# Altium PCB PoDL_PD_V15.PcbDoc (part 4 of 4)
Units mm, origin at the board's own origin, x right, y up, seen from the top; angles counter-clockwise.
Board outline 145 x 75 mm, 4 copper layers (Top Layer, Signal Layer 2, Signal Layer 3, Bottom Layer), stack 1.586 mm thick; 346 components, 228 nets, 1035 pads, 619 vias.
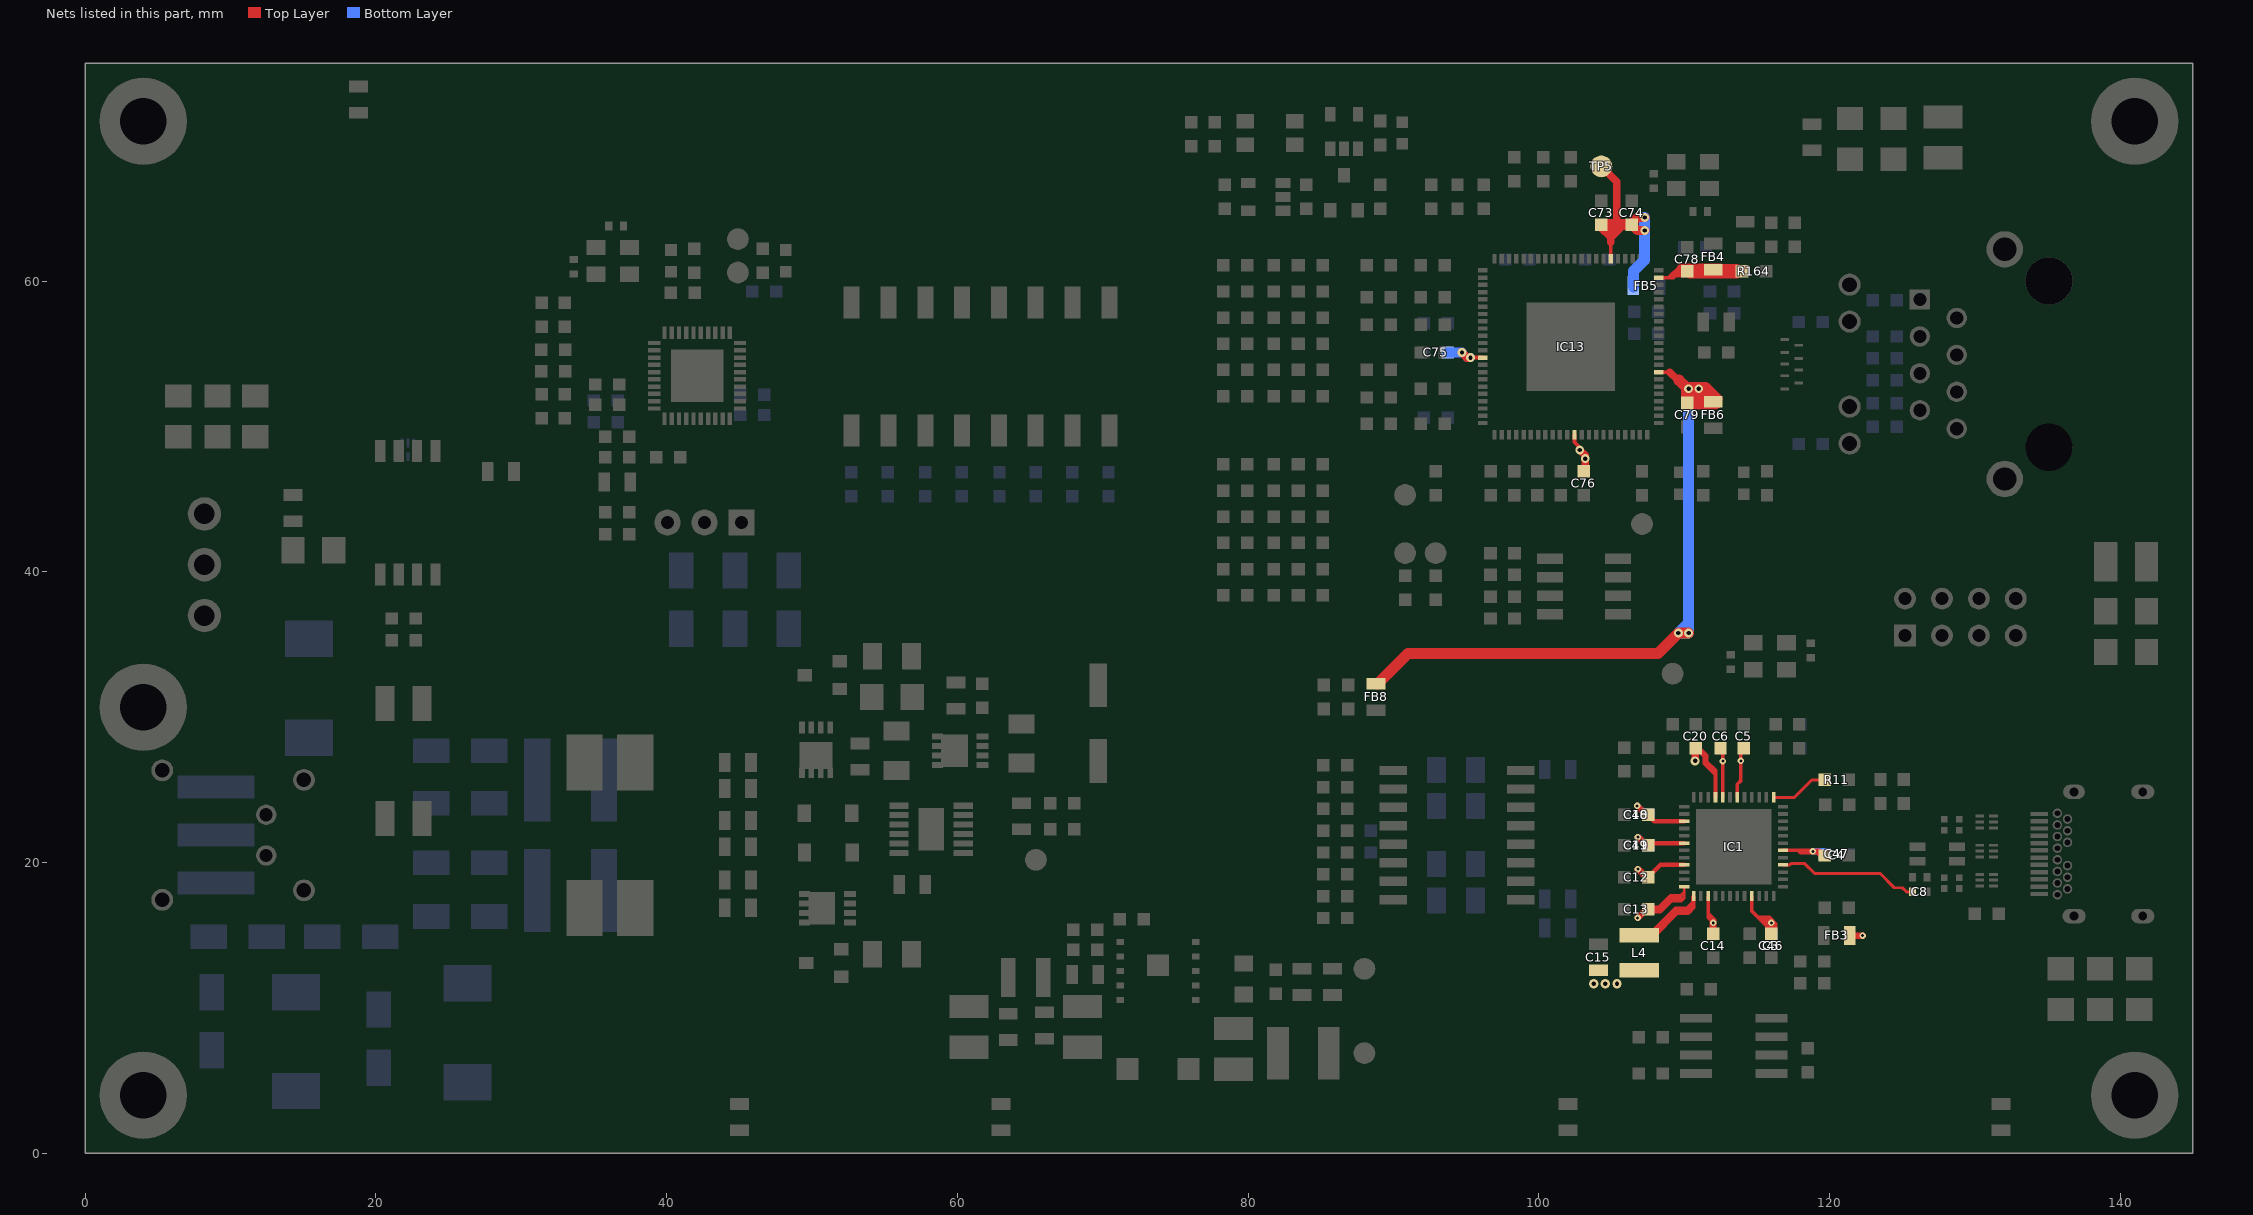
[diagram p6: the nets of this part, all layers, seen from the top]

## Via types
v1: diameter 0.6, hole 0.3, Top Layer to Bottom Layer, tented both sides, 350 vias
v2: diameter 0.45, hole 0.2, Top Layer to Bottom Layer, tented both sides, 137 vias
v3: diameter 0.635, hole 0.3, Top Layer to Bottom Layer, tented both sides, 77 vias
v4: diameter 1.016, hole 0.508, Top Layer to Bottom Layer, 40 vias
v5: diameter 1.016, hole 0.457, Top Layer to Bottom Layer, tented both sides, 8 vias
v6: diameter 0.762, hole 0.381, Top Layer to Bottom Layer, tented both sides, 7 vias

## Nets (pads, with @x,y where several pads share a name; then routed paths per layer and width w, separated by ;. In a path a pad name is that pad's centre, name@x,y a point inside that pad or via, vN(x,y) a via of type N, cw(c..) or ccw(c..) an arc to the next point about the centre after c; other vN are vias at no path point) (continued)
USB3TX_P: C8.2 IC1.28 | length 9.8
  Top Layer w0.206: IC1.28@116.8,19.85 117.253,19.85 117.336,19.934 118.301,19.934 118.967,19.267 123.461,19.267 124.451,18.277 125.005,18.277 125.302,17.98 C8.2@125.725,17.98
USBRBIAS: IC1.37 R11.1 | length 4
  Top Layer w0.203: IC1.37@116.15,24.5 117.595,24.5 118.8,25.705 R11.1@119.675,25.705
VDD12: C3.1 C4.1 C5.1 C6.1 C14.1 C15.2 C46.1 C47.1 FB3.2 IC1.15 IC1.21 IC1.30 IC1.42 IC1.44 L4.2 | length 24.5
  Top Layer w0.25: IC1.15@111.65,17.7 111.65,16.521 ; C14.1@111.995,15.061 111.868,15.188 111.868,16.013 111.65,16.231 111.65,16.521 ; C14.1@112.1,15.166 112.1,15.861 112.1,16.071 111.65,16.521 ; IC1.44@112.65,24.5 C6.1@112.65,27.73 ; IC1.42@113.65,24.5 113.65,25.405 113.9,25.655 C5.1@113.9,27.48 ; IC1.21@114.65,17.7 114.65,16.681 115.1,16.231 ; C3.1@115.7,15.188 115.7,15.631 115.413,15.918 115.1,16.231 ; C3.1@116,15.081 116.3,15.381 116.3,15.807 115.876,16.231 115.55,16.231 115.1,16.231 ; IC1.30@116.8,20.85 117.828,20.85 ; 117.828,20.85 117.978,20.7 118.853,20.7 119.125,20.7 119.345,20.48 119.7,20.48 119.33,20.85 118.853,20.85 117.828,20.85
  Top Layer w0.45: FB3.2@121.4,14.98 v2(122.274,14.98)
  Top Layer w0.508: 115.55,16.055 115.837,15.768 116,15.605 C3.1@116,15.081
  Bottom Layer w0.45: v2(118.853,20.78) C47.1@119.627,20.78
  Bottom Layer w0.508: C46.1@116,15.08 v2(116,15.855)
  other v2: 111.995,15.861 112.655,26.985 113.9,27
  other v3: 103.775,11.68 104.575,11.68 105.375,11.68
VDD12_SW_OUT: IC1.13 L4.1 | length 12.7
  Top Layer w0.25: L4.1@107.477,14.927 109.405,16.855 110.18,16.855 110.6,17.275 IC1.13@110.6,17.655 ; L4.1@107.672,14.927 109.4,16.655 110.25,16.655 110.575,16.98 110.65,17.055 ; L4.1@107.936,14.927 109.53,16.521 110.266,16.521 110.325,16.58 110.65,16.905 110.65,17.055 ; IC1.13@110.65,17.7 110.65,17.275 110.65,17.055
VDD25: C10.1 C11.1 C12.1 C13.1 C20.1 C48.1 C49.1 IC1.3 IC1.6 IC1.9 IC1.12 IC1.45 | length 29.6
  Top Layer w0.2: C13.1@107.5,16.78 C13.1@107.606,16.675 ; C13.1@107.606,16.6 108.38,16.6 109.13,17.35 109.77,17.35 110,17.58 110,17.98 ; C13.1@107.67,16.95 108.245,16.95 109.045,17.75 109.77,17.75 110,17.98 ; IC1.12@110,18.35 110,17.98
  Top Layer w0.25: C13.1@107.5,16.78 108.335,16.78 109.087,17.532 109.675,17.532 109.77,17.627 109.77,17.75 ; C20.1@110.884,27.804 111.4,27.288 111.4,26.805 112.15,26.055 ; C20.1@111.051,27.879 111.55,27.38 111.55,26.955 112.15,26.355 112.15,26.055 ; IC1.45@112.15,24.5 112.15,26.055
  Top Layer w0.305: C12.1@107.5,18.98 108.37,19.85 IC1.9@110,19.85 ; C11.1@107.5,21.18 107.67,21.35 IC1.6@110,21.35 ; C10.1@107.5,23.28 107.931,22.85 IC1.3@110,22.85
  Top Layer w0.45: v2(106.763,23.912) C10.1@107.345,23.33 ; v2(106.8,16.2) C13.1@107.382,16.782 ; v2(106.813,19.562) C12.1@107.395,18.98 ; v2(106.813,21.762) C11.1@107.395,21.18 ; C13.1@107.5,16.78 C13.1@107.67,16.95
  Top Layer w0.508: v3(110.75,27.005) C20.1@110.75,27.78
  Bottom Layer w0.45: v2(106.763,23.912) 107.375,23.3 C48.1@107.526,23.3 ; v2(106.813,21.762) C49.1@107.425,21.15
VDD33TXRX1: C79.1 FB6.2 FB8.2 IC13.74 | length 51.8
  Top Layer w0.254: IC13.74@108.25,53.75 109.012,53.75
  Top Layer w0.508: 109.012,53.75 109.572,53.19
  Top Layer w0.762: FB8.2@88.9,32.3 91,34.4 108.2,34.4 v1(109.6,35.8) v1(110.3,35.8) ; 109.647,53.19 v1@110.155,52.682 ; C79.1@110.155,51.666 110.155,52.3 ; 111.125,51.7 111.125,51.712 ; 111.468,52.3 110.155,52.3 ; FB6.2@112.25,51.9 111.468,52.682 v1@110.155,52.682 ; 110.155,52.3 v1@110.155,52.682
  Top Layer w1.016: C79.1@110.3,51.7 111.125,51.7 FB6.2@112,51.7 FB6.2@112.1,51.7
  Bottom Layer w0.762: 110.3,36.5 v1(109.6,35.8) v1(110.3,35.8) 110.3,36.5 ; 110.3,36.5 110.3,52 ; 110.3,52 110.4,52 v1(111,52.6) v1(110.3,52.6) 110.3,52
VDD33TXRX2: C78.1 FB4.2 IC13.87 R164.1 | length 9
  Top Layer w0.254: IC13.87@108.25,60.25 108.944,60.25 ; 109.686,60.674 109.386,60.375 ; 109.758,61.064 108.944,60.25 ; C78.1@109.875,60.375 109.386,60.375 ; 108.944,60.25 109.262,60.25 109.386,60.375
  Top Layer w0.762: C78.1@109.85,60.825 FB4.2@112.45,60.825
  Top Layer w1.016: C78.1@110.409,60.683 R164.1@113.557,60.683
VDDCR: C73.2 C74.1 C75.1 C76.1 FB5.2 IC13.6 IC13.35 IC13.56 TP5.1 | length 22.5
  Top Layer w0.254: v1@95.248,54.75 v1(95.3,54.75) IC13.35@96.15,54.75 ; IC13.56@102.45,49.45 102.45,48.922 102.74,48.632 v1@102.74,48.594 ; IC13.6@104.95,61.55 104.95,62.688
  Top Layer w0.508: v1(102.816,48.391) 103.185,48.022 C76.1@103.185,47.207 ; TP5.1@104.3,67.9 105.356,66.844 105.356,63.831 ; 104.95,62.688 104.95,63.171 104.95,63.679
  Top Layer w0.6: v1(94.715,55.095) 95.06,54.75 v1@95.248,54.75
  Top Layer w0.635: C74.1@106.4,63.875 106.781,63.494 v1(107.289,63.494) ; C74.1@106.4,64.002 106.781,64.383 v1(107.289,64.383)
  Top Layer w0.762: C73.2@104.368,63.9 105.003,63.9 ; C73.2@104.417,63.704 104.95,63.171 105.483,63.704 ; 105.511,63.9 C74.1@106.4,63.9
  Bottom Layer w0.6: v1(94.715,55.095) 95.059,54.75 v1(95.3,54.75)
  Bottom Layer w0.7: C75.1@93.725,55.1 93.731,55.095 v1(94.715,55.095)
  Bottom Layer w0.762: FB5.2@106.499,59.6 106.499,60.699 107.261,61.461 v1@107.261,64.383
  other v1: 103.2,47.8
pads on no net: D2.4 D3.4 D4.4 D17.4 D26.1 D26.5 D26.6 D26.9 IC1.7 IC1.8 IC1.10 IC1.11 IC2.8 IC2.11 IC3.7 IC4.6 IC9.10 IC9.11 IC9.18 IC9.21 IC10.1 IC11.1 IC13.3 IC13.11 IC13.18 IC13.29 IC13.31 IC13.45 IC13.67 IC13.68 IC13.88 X1.A4 X1.A8 X1.A9 X1.A10 X1.A11 X1.B2 X1.B3 X1.B4 X1.B5 X1.B8 X1.B9 X7.H1 X7.H2 X7.P7 X8.4 X8.5 X8.12 X8.13

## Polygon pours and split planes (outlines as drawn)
+3V3 on Top Layer "Top Layer-+3V3" (solid, remove dead copper, pour order 84): 84.8,4.3 84.8,9.3 84.6,9.5 81.6,9.5 81.4,9.7 81.4,11.4 81.5,11.5 88.95,11.5 89.182,11.268 89.182,4.308 88.874,4 85.074,4 84.8,4.274
NetC106_1 on Top Layer "Top Layer-NetC124_1" (solid, remove dead copper, pour order 82): 70.8,4.274 71.075,4 82.5,4 82.8,4.3 82.8,8.8 82.7,8.9 81.241,8.9 81.1,8.759 81.1,7.1 80.6,6.6 71,6.6 70.8,6.4
NetC26_1 on Top Layer "Top Layer-NetC26_1" (solid, remove dead copper, pour order 80): 65.3,9.1 71.4,9.1 71.5,9.2 71.5,11.735 71.4,11.835 70.935,11.835 70.8,11.7 70.2,11.1 66.9,11.1 66.6,11.4 66.6,13.5 66.425,13.675 65.469,13.675 65.4,13.606 65.4,10.739 65.2,10.539 65.2,9.2
GND on Top Layer "Top Layer-GND" (solid, remove dead copper, pour order 30): 133.2,10.9 134.2,11.9 142,11.9 142.4,12.3 142.4,25.5 139.8,28.1 139.8,42.9 139.4,43.3 130.717,43.3 129.9,44.117 129.9,68.775 129.275,69.45 118.15,69.45 115.2,72.4 17,72.4 10.7,72.4 4.7,66.4 4.7,51.7 5.2,51.2 14.1,51.2 17.2,48.1 17.2,45.9 17.787,45.313 31.237,45.313 31.725,44.825 31.725,33 32.525,32.2 42.357,32.2 43,31.557 43,30 43,2.7 132.6,2.7 133.2,3.3
SHIELD on Top Layer "Top Layer-SHIELD" (solid, remove dead copper, pour order 22): 133.95,2.35 133.95,10.25 134.5,10.8 142.6,10.8 143.3,11.5 143.3,26.1 140.9,28.5 140.9,43.3 140,44.2 131.323,44.2 130.823,44.7 130.823,68.989 129.612,70.2 118.196,70.2 115.396,73 14.6,73 9.2,73 3.8,67.6 3.8,51.4 5,50.2 12.7,50.2 13.6,49.3 15.5,47.4 15.5,44.7 15.2,44.4 11.3,44.4 9.9,43 5.6,43 5.2,42.6 5.2,34.6 5.7,34.1 7.2,34.1 7.8,33.5 7.8,28.4 8.5,27.7 15.048,27.7 15.6,27.148 15.6,25.2 6.7,25.2 6.2,24.7 6.2,19.1 6.7,18.6 15.6,18.6 15.6,16.7 15.2,16.3 4.345,16.3 3.8,15.755 3.8,7.6 9.4,2 13.6,2 13.6,0 0,0 0,75 145,75 145,0 43,0 43,2 133.6,2
NetC35_1 on Top Layer "Top Layer-NetC35_1" (solid, remove dead copper, pour order 20): 67.7,25 67.4,25.3 67.4,27.9 66.8,28.5 63.1,28.5 63,28.6 63,30.9 63.2,31.1 67.575,31.1 68,30.675 68,29.7 68.494,29.206 71.019,29.206 71.425,28.8 71.425,25.481 70.944,25
PWR_OUT on Top Layer "Top Layer-PWR_OUT" (solid, remove dead copper, pour order 14): 62.775,18.575 63.2,19 63.2,22.9 63.5,23.2 66.8,23.2 67.2,22.8 67.2,19.1 64,15.9 64,10.734 64.3,10.434 64.3,9 64.1,8.8 59.2,8.8 58.9,9.1 58.9,11.9 59.3,12.3 61.3,12.3 61.6,12.6 61.6,17.4
NetC96_1 on Top Layer "Top Layer-NetFB10_1" (solid, remove dead copper, pour order 12): 62.729,23.275 66.875,23.275 67.187,23.587 67.187,27.759 66.646,28.3 62.4,28.3 62.3,28.2 61.4,28.2 61.3,28.1 61.3,25.609 61.6,25.309 61.6,23.6 61.1,23.1 62.554,23.1
NetC1_1 on Top Layer "Top Layer-NetC1_1" (solid, remove dead copper, pour order 10): 51.5,24.6 52,25.1 52,27 52.2,27.2 54.363,27.2 54.737,27.575 57.175,27.575 57.4,27.8 57.4,29.15 57.65,29.4 60.5,29.4 60.7,29.2 60.7,26.2 60.5,26 57.9,26 57.1,25.2 54.8,25.2 53.9,24.3 53.9,19.7 53.6,19.4 51.7,19.4 51.5,19.6
GND on Top Layer "GND_OSC" (solid, remove dead copper, pour order 6): 112.475,31.803 112.175,32.103 112.175,36.503 112.475,36.803 119.345,36.803 119.669,36.479 119.669,32.048 119.425,31.803
+3V3 on Top Layer "+3V3_L01_P004" (hatched Horizontal grid 0.203 track 0.203, remove dead copper, pour order 4): 108.92,26.97 108.92,27.55 109.38,27.55 109.45,27.48 109.45,27.155 110.3,26.305 111.3,26.305 111.65,25.955 111.65,25.288 111.133,25.805 110.085,25.805
+3V3 on Top Layer "+3V3_L01_P002" (hatched Horizontal grid 0.203 track 0.203, remove dead copper, pour order 2): 117.6,26.205 117.6,27.48 118.2,27.48 118.2,26.005 117.576,25.381 117,25.381 117,25.605
+3V3 on Top Layer "+3V3_L01_P000" (hatched Horizontal grid 0.203 track 0.203, remove dead copper, pour order 0): 116,26.805 115.15,25.955 115.15,25.605 115.595,26.05 116.445,26.05 116.6,26.205 116.6,27.48 116.338,27.742 116,27.742
GND on Signal Layer 2 "Signal Layer 2-GND" (solid, remove dead copper, pour order 44): 132.4,2.7 132.6,2.7 133.2,3.3 133.2,10.9 134.2,11.9 142,11.9 142.4,12.3 142.4,25.5 139.8,28.1 139.8,42.9 139.4,43.3 130.717,43.3 129.9,44.117 129.9,68.775 129.275,69.45 118.15,69.45 115.2,72.4 17,72.4 10.7,72.4 4.7,66.4 4.7,51.7 5.2,51.2 14.1,51.2 17.2,48.1 17.2,45.9 17.787,45.313 31.237,45.313 31.725,44.825 31.725,33 32.525,32.2 42.357,32.2 43,31.557 43,29.987 43,2.7
SHIELD on Signal Layer 2 "Signal Layer 2-SHIELD 2" (solid, remove dead copper, pour order 38): 133.6,2 133.95,2.35 133.95,10.25 134.5,10.8 142.6,10.8 143.3,11.5 143.3,26.1 140.9,28.5 140.9,43.3 140,44.2 131.323,44.2 130.823,44.7 130.823,68.989 129.612,70.2 118.196,70.2 115.396,73 14.6,73 9.2,73 3.8,67.6 3.8,51.4 5,50.2 12.7,50.2 15.5,47.4 15.5,44.7 15.2,44.4 11.3,44.4 9.9,43 5.6,43 5.2,42.6 5.2,34.6 5.7,34.1 7.2,34.1 7.8,33.5 7.8,28.4 8.5,27.7 15.048,27.7 15.6,27.148 15.6,25.2 6.7,25.2 6.2,24.7 6.2,19.1 6.7,18.6 15.6,18.6 15.6,16.7 15.2,16.3 4.345,16.3 3.8,15.755 3.8,7.6 9.4,2 13.6,2 13.6,0 0,0 0,75 145,75 145,0 43,0 43,2
NetD12_2 on Bottom Layer "Bottom Layer-NetD12_2" (solid, remove dead copper, pour order 68): 6.8,7.3 7.3,7.8 21.5,7.8 21.9,7.4 21.9,2.8 21.4,2.3 7.3,2.3 6.8,2.8
NetD11_1 on Bottom Layer "Bottom Layer-NetD11_1" (solid, remove dead copper, pour order 66): 10.8,16 10.8,9.2 11.1,8.9 17.6,8.9 18.1,9.4 18.1,16.2 17.9,16.4 11.2,16.4
GND on Bottom Layer "Bottom Layer-GND" (solid, remove dead copper, pour order 48): 133.2,10.9 134.217,11.917 142.017,11.917 142.4,12.3 142.4,25.505 139.8,28.105 139.8,30.011 139.8,42.9 139.4,43.3 130.717,43.3 129.9,44.117 129.9,68.775 129.275,69.45 118.15,69.45 115.2,72.4 17,72.4 10.7,72.4 4.7,66.4 4.7,51.7 5.2,51.2 14.1,51.2 17.2,48.1 17.2,45.9 17.787,45.313 31.237,45.313 35.787,45.313 39.2,41.9 39.2,32.678 39.736,32.2 42.357,32.2 43,31.557 43,30 43,2.7 132.6,2.7 133.2,3.3
SHIELD on Bottom Layer "Bottom Layer-SHIELD 1" (solid, remove dead copper, pour order 36): 133.6,2 133.95,2.35 133.95,10.25 134.5,10.8 142.6,10.8 143.3,11.5 143.3,26.1 140.9,28.5 140.9,28.7 140.9,43.3 140,44.2 131.323,44.2 130.823,44.7 130.823,68.989 129.612,70.2 118.196,70.2 115.396,73 14.6,73 9.2,73 3.8,67.6 3.8,51.4 5,50.2 12.7,50.2 15.5,47.4 15.5,43.817 16.7,42.617 16.7,35 14.1,35 14.1,41.1 12.2,43 9.9,43 5.6,43 5.2,42.6 5.2,34.6 5.7,34.1 7.2,34.1 7.8,33.5 7.8,28.85 5.3,26.35 5.3,17.45 5.7,17.05 5.7,16.33 4.375,16.33 3.8,15.755 3.8,7.6 9.4,2 13.6,2 13.6,0 0,0 0,75 145,75 145,0 43,0 43,2
GND on Signal Layer 3 "Signal Layer 3-GND" (solid, remove dead copper, pour order 58): 133.2,10.9 134.2,11.9 142,11.9 142.4,12.3 142.4,25.497 139.8,28.097 139.8,29.029 139.8,42.9 139.4,43.3 130.717,43.3 129.9,44.117 129.9,68.775 129.275,69.45 118.15,69.45 115.2,72.4 17,72.4 10.7,72.4 4.7,66.4 4.7,51.7 5.2,51.2 14.1,51.2 17.2,48.1 17.2,45.9 17.787,45.313 31.237,45.313 31.725,44.825 31.725,33 32.525,32.2 42.357,32.2 43,31.557 43,29.9 43,2.7 132.6,2.7 133.2,3.3
VDD12 on Signal Layer 3 "Signal Layer 3-VDD12" (solid, remove dead copper, pour order 56): 103.4,11.2 108.738,11.2 109.4,11.862 109.4,15.3 109.6,15.5 112.747,15.5 112.9,15.653 112.9,16.137 113.093,16.33 115.265,16.33 115.395,16.2 115.395,14.905 115.6,14.7 122.4,14.7 122.55,14.85 122.55,15.45 122.347,15.653 119.747,15.653 119.4,16 119.4,26.6 118.6,27.4 112.4,27.4 112.212,27.212 112.212,26.583 112.395,26.4 117.953,26.4 118.3,26.053 118.3,17.6 118,17.3 109.02,17.3 108.2,16.48 108.2,12.6 108,12.4 103.5,12.4 103.3,12.2 103.3,11.3
VDD25 on Signal Layer 3 "Signal Layer 3-VDD25" (solid, remove dead copper, pour order 54): 106.1,16 106.3,15.8 107.2,15.8 107.4,16 107.4,26.2 107.826,26.626 111.048,26.626 111.229,26.807 111.229,27.691 111.019,27.9 107,27.9 106.1,27
+3V3 on Signal Layer 3 "Signal Layer 3-+3V3" (solid, remove dead copper, pour order 52): 79.8,5.1 79.2,5.7 79.2,43.5 77.6,45.1 34.3,45.1 33.9,45.5 33.9,59.4 34.6,60.1 73.6,60.1 75.4,61.9 75.4,71.2 76.1,71.9 114.7,71.9 117.5,69.1 117.5,49.703 117.54,47.76 126.4,38.9 126.4,34.7 123.9,32.2 123.9,13.1 128,9 129.1,7.9 129.1,5.4 128.8,5.1
VDDCR on Signal Layer 3 "Signal Layer 3-VDDCR" (solid, remove dead copper, pour order 50): 102.8,47.4 102.5,47.7 102.5,51.1 102.1,51.5 94.55,51.5 94.3,51.75 94.3,55.4 94.5,55.6 98.3,55.6 98.5,55.8 98.5,59.715 98.8,60.015 106.515,60.015 106.8,60.3 106.8,64.6 107.1,64.9 108.3,64.9 108.5,64.7 108.5,49.8 108.2,49.5 106.3,49.5 106.1,49.3 106.1,47.621 105.879,47.4
SHIELD on Signal Layer 3 "Signal Layer 3-SHIELD" (solid, remove dead copper, pour order 42): 133.6,2 133.95,2.35 133.95,10.25 134.5,10.8 142.6,10.8 143.3,11.5 143.3,26.1 140.9,28.5 140.9,43.3 140,44.2 131.323,44.2 130.823,44.7 130.823,68.989 129.612,70.2 118.196,70.2 115.396,73 14.6,73 9.2,73 3.8,67.6 3.8,51.4 5,50.2 12.7,50.2 15.5,47.4 15.5,44.7 15.2,44.4 11.3,44.4 9.9,43 5.6,43 5.2,42.6 5.2,33.6 7.8,31 7.8,28.4 8.5,27.7 15.048,27.7 15.6,27.148 15.6,25.422 15.378,25.2 6.7,25.2 6.2,24.7 6.2,19.1 6.7,18.6 15.6,18.6 15.6,16.7 15.2,16.3 4.345,16.3 3.8,15.755 3.8,7.6 9.4,2 13.6,2 13.6,0 0,0 0,75 145,75 145,0 43,0 43,2

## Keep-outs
Keep-Out Layer:
  the board outline again, w0.2

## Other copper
Top Layer:
  rectangle net +3V3: 84.8,4.7 86.8,11.5
  rectangle net +3V3: 81.4,9.9 85.4,11.5
  rectangle net SHIELD: 12.8,0.4 43.5,2
  region net GND: 119.45,34.354 118.15,34.354 118.15,33.1 119.45,33.1
  region net GND: 118.481,34.2 116.5,34.2 116.5,32.325 118.481,32.325
  rectangle net GND: 113.565,34.421 115.811,36.1
  rectangle net GND: 112.45,34.046 113.75,35.3
  rectangle net VDD12: 103.275,11.08 108.38,12.98
  rectangle net NetC57_1: 36.7,52.75 39.15,53.3
  pour cut-out: 64,10.734 64,13.44 64.06,13.5 65.34,13.5 65.4,13.44 65.4,10.739 65.361,10.7 64.034,10.7
  region net P0_IND1: 64.3,47
  region net +3V3: 49.175,60.65
  region net +3V3: 39.3,59.2
  region: 4.8,32.4
  pour cut-out: 115.05,31.78 112.55,31.78 112.2,32.13 112.2,36.53 112.5,36.83 119.37,36.83 119.695,36.505 119.695,32.075 119.4,31.78 115.495,31.78 115.495,31.557 119.538,31.557 119.919,31.938 119.919,36.637 119.513,37.044 112.375,37.044 111.994,36.663 111.994,31.938 112.375,31.557 115.05,31.557
  text "Top Layer" at 58.2,80.3 h1.8
Signal Layer 2:
  rectangle net SHIELD: 12.8,0.4 43.5,2
  pour cut-out: 64,10.734 64,13.44 64.06,13.5 65.34,13.5 65.4,13.44 65.4,10.739 65.361,10.7 64.034,10.7
  pour cut-out: 82.8,5.1 82.8,8.7 82.918,8.818 84.682,8.818 84.8,8.7 84.8,5.1 84.7,5 82.9,5
  text "Inner Layer2 (GND Plane)" at 46.2,80.2 h1.8
Signal Layer 3:
  rectangle net SHIELD: 12.8,0.4 43.5,2
  pour cut-out: 82.8,5.1 82.8,8.7 82.918,8.818 84.682,8.818 84.8,8.7 84.8,5.1 84.7,5 82.9,5
  pour cut-out: 64,10.734 64,13.44 64.06,13.5 65.34,13.5 65.4,13.44 65.4,10.739 65.361,10.7 64.034,10.7
  pour cut-out: 140.797,24.6 140.797,16.8 135.337,16.8 135.3,16.763 135.3,24.6
  text "Inner Layer3 (Power/GND Plane)" at 45.2,80.6 h1.8
Bottom Layer:
  region net SHIELD: 27.5,5.2 25.1,5.2 25.1,0.9 27.5,0.9
  rectangle net SHIELD: 14.1,34.7 16.7,37.7
  region net NetL1_3: 35.6,21 33.4,21 33.4,13.7 35.6,13.7
  rectangle net NetL1_2: 33.4,22.85 35.6,30.15
  region net POWER/DATA_N: 19,16 19,8.5 21.3,8.5 21.3,16
  rectangle net GND: 99.1,14.772 100.699,16.121
  region net POWER/DATA_P: 7.5,16.1 7.5,8.6 9.8,8.6 9.8,16.1
  rectangle net SHIELD: 12.8,0.4 43.5,2
  rectangle net +3V3: 46,49.3 47.6,53.6
  pour cut-out: 82.8,5.1 82.8,8.7 82.918,8.818 84.682,8.818 84.8,8.7 84.8,5.1 84.7,5 82.9,5
  pour cut-out: 64,10.734 64,13.44 64.06,13.5 65.34,13.5 65.4,13.44 65.4,10.739 65.361,10.7 64.034,10.7
  region: 4.8,32.4
  pour cut-out: 139.7,24.6 139.7,16.8 135.337,16.8 135.3,16.763 135.3,24.6
  text "Bottom Layer" at 73.4,80.3 h1.8

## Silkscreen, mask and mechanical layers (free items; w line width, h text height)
Top Overlay:
  text "RESET" at 79.9,72.5 h0.76
  text "P0" at 74.9,62.2 h0.89
  text "MODE3" at 73.8,60.7 h0.76
  text "MEDIA_CNV" at 53.1,60.294 h0.76 r90
  text "MACIF_SEL1" at 55.64,60.294 h0.76 r90
  text "SWPD_N" at 58.16,60.294 h0.76 r90
  text "MACIF_SEL0" at 60.7,60.294 h0.76 r90
  text "TX2P4_DIS" at 63.24,60.294 h0.76 r90
  text "MS_SEL" at 65.76,60.294 h0.76 r90
  text "PHYAD_0" at 68.3,60.294 h0.76 r90
  text "PHYAD_1" at 70.84,60.294 h0.76 r90
  text "MODE2" at 73.8,59 h0.76
  text "MODE1" at 73.8,57.2 h0.76
  text "MODE0" at 73.8,55.4 h0.76
  text "SPEED" at 73.8,53.544 h0.76
  text "DUPLEX" at 73,51.7 h0.76
  text "P1" at 74.9,48.5 h0.89
  text "MODE3" at 73.8,47 h0.76
  text "MODE2" at 73.8,45.3 h0.76
  text "SHD" at 10.1,43.5 h1
  text "MODE1" at 73.8,43.5 h0.76
  text "MODE0" at 73.8,41.7 h0.76
  text "LINK" at 109.1,41.3 h0.76
  text "SPEED" at 113.5,41.3 h0.76
  text "3V3" at 125.65,40.07 h0.76 r90
  text "WP" at 128.19,40.07 h0.76 r90
  text "SCL" at 130.73,40.07 h0.76 r90
  text "SDA" at 133.27,40.07 h0.76 r90
  text "D_P" at 10.2,40 h1
  text "/ACT" at 108.8,40 h0.76
  text "SPEED" at 73.8,39.844 h0.76
  text "INT" at 40.4,39.7 h0.76 r90
  text "MDC" at 45.6,39.5 h0.76 r90
  text "MDIO" at 43,38.9 h0.76 r90
  text "DUPLEX" at 73,38 h0.76
  text "D_N" at 10.2,36.6 h1
  text "1" at 123.158,35.15 h0.76
  text "A0" at 125.62,32.6 h0.76 r90
  text "A1" at 128.16,32.6 h0.76 r90
  text "A2" at 130.7,32.6 h0.76 r90
  text "GND" at 133.2,31.8 h0.76 r90
  text "EEPROM" at 123.922,30.5 h1
  text "Programming" at 124,28.7 h1
  text "GND" at 89.043,12.1 h0.76
  text "3V3" at 89.2,6.5 h0.76
Bottom Overlay:
  text "PoDL - PD V1.5" at 41.8,69.7 h3
  text "Pr.No.: 749950" at 41.8,66.7 h3
  text "Würth Elektronik eiSos" at 41.8,63.7 h2.2
  text "Max - Eyth - Str. 1" at 41.8,61 h2.2
  text "74638 Waldenburg" at 41.8,58.3 h2.2
  text "Germany" at 41.8,55.6 h2.2
Mechanical 1:
  drawing of 295 lines, arcs and shapes, not listed
  text "Layer" at 166.319,14.336 h1.52
  text "Name" at 176.731,14.336 h1.52
  text "Material" at 200.6,14.336 h1.52
  text "Thickness" at 222.438,14.336 h1.52
  text "Constant" at 238.944,14.336 h1.52
  text "Board Layer Stack" at 253.418,14.336 h1.52
  text "1" at 166.319,11.288 h1.52
  text "Top Overlay" at 176.731,11.288 h1.52
  text "2" at 166.319,8.24 h1.52
  text "Top Solder" at 176.731,8.24 h1.52
  text "Solder Resist" at 200.6,8.24 h1.52
  text "0.010mm" at 222.438,8.24 h1.52
  text "3.8" at 238.944,8.24 h1.52
  text "3" at 166.319,5.192 h1.52
  text "Top Layer" at 176.731,5.192 h1.52
  text "Copper" at 200.6,5.192 h1.52
  text "0.035mm" at 222.438,5.192 h1.52
  text "4" at 166.319,2.144 h1.52
  text "Dielectric 1" at 176.731,2.144 h1.52
  text "7628" at 200.6,2.144 h1.52
  text "0.210mm" at 222.438,2.144 h1.52
  text "4.6" at 238.944,2.144 h1.52
  text "5" at 166.319,-0.904 h1.52
  text "Signal Layer 2" at 176.731,-0.904 h1.52
  text "Copper" at 200.6,-0.904 h1.52
  text "0.015mm" at 222.438,-0.904 h1.52
  text "6" at 166.319,-3.952 h1.52
  text "Dielectric 3" at 176.731,-3.952 h1.52
  text "Core-009" at 200.6,-3.952 h1.52
  text "1.065mm" at 222.438,-3.952 h1.52
  text "4.6" at 238.944,-3.952 h1.52
  text "7" at 166.319,-7 h1.52
  text "Signal Layer 3" at 176.731,-7 h1.52
  text "Copper" at 200.6,-7 h1.52
  text "0.015mm" at 222.438,-7 h1.52
  text "8" at 166.319,-10.048 h1.52
  text "Dielectric 2" at 176.731,-10.048 h1.52
  text "PP-006" at 200.6,-10.048 h1.52
  text "0.210mm" at 222.438,-10.048 h1.52
  text "4.6" at 238.944,-10.048 h1.52
  text "9" at 166.319,-13.096 h1.52
  text "Bottom Layer" at 176.731,-13.096 h1.52
  text "Copper" at 200.6,-13.096 h1.52
  text "0.035mm" at 222.438,-13.096 h1.52
  text "10" at 166.319,-16.144 h1.52
  text "Bottom Solder" at 176.731,-16.144 h1.52
  text "Solder Resist" at 200.6,-16.144 h1.52
  text "0.010mm" at 222.438,-16.144 h1.52
  text "3.8" at 238.944,-16.144 h1.52
  text "11" at 166.319,-19.192 h1.52
  text "Bottom Overlay" at 176.731,-19.192 h1.52
Drill Drawing:
  drawing of 181 lines, arcs and shapes, not listed
  text "Symbol" at 167.815,88.61 h1.83
  text "Count" at 180.664,88.61 h1.83
  text "Hole Size" at 195.9,88.61 h1.83
  text "Plated" at 225.101,88.61 h1.83
  text "Hole Type" at 237.951,88.61 h1.83
  text "Drill Layer Pair" at 256.589,88.61 h1.83
  text "Via/Pad" at 294.678,88.61 h1.83
  text "Pad Shape" at 309.66,88.61 h1.83
  text "2" at 180.664,84.8 h1.52
  text "1.600mm (62.99mil)" at 195.9,84.8 h1.52
  text "PTH" at 225.101,84.8 h1.52
  text "Round" at 237.951,84.8 h1.52
  text "Top Layer - Bottom Layer" at 256.589,84.8 h1.52
  text "Pad" at 294.678,84.8 h1.52
  text "Rounded" at 309.66,84.8 h1.52
  text "2" at 180.664,80.99 h1.52
  text "3.250mm (127.95mil)" at 195.9,80.99 h1.52
  text "NPTH" at 225.101,80.99 h1.52
  text "Round" at 237.951,80.99 h1.52
  text "Top Layer - Bottom Layer" at 256.589,80.99 h1.52
  text "Pad" at 294.678,80.99 h1.52
  text "Rounded" at 309.66,80.99 h1.52
  text "3" at 180.664,77.18 h1.52
  text "1.400mm (55.12mil)" at 195.9,77.18 h1.52
  text "PTH" at 225.101,77.18 h1.52
  text "Round" at 237.951,77.18 h1.52
  text "Top Layer - Bottom Layer" at 256.589,77.18 h1.52
  text "Pad" at 294.678,77.18 h1.52
  text "Rounded" at 309.66,77.18 h1.52
  text "4" at 180.664,73.37 h1.52
  text "0.600mm (23.62mil)" at 195.9,73.37 h1.52
  text "PTH" at 225.101,73.37 h1.52
  text "Slot" at 237.951,73.37 h1.52
  text "Top Layer - Bottom Layer" at 256.589,73.37 h1.52
  text "Pad" at 294.678,73.37 h1.52
  text "Rounded" at 309.66,73.37 h1.52
  text "4" at 180.664,69.56 h1.52
  text "1.000mm (39.37mil)" at 195.9,69.56 h1.52
  text "PTH" at 225.101,69.56 h1.52
  text "Round" at 237.951,69.56 h1.52
  text "Top Layer - Bottom Layer" at 256.589,69.56 h1.52
  text "Pad" at 294.678,69.56 h1.52
  text "Rounded" at 309.66,69.56 h1.52
  text "4" at 180.664,65.75 h1.52
  text "1.020mm (40.16mil)" at 195.9,65.75 h1.52
  text "PTH" at 225.101,65.75 h1.52
  text "Round" at 237.951,65.75 h1.52
  text "Top Layer - Bottom Layer" at 256.589,65.75 h1.52
  text "Pad" at 294.678,65.75 h1.52
  text "Rounded" at 309.66,65.75 h1.52
  text "5" at 180.664,61.94 h1.52
  text "3.200mm (125.98mil)" at 195.9,61.94 h1.52
  text "PTH" at 225.101,61.94 h1.52
  text "Round" at 237.951,61.94 h1.52
  text "Top Layer - Bottom Layer" at 256.589,61.94 h1.52
  text "Pad" at 294.678,61.94 h1.52
  text "Rounded" at 309.66,61.94 h1.52
  text "7" at 180.664,58.13 h1.52
  text "0.381mm (15.00mil)" at 195.9,58.13 h1.52
  text "PTH" at 225.101,58.13 h1.52
  text "Round" at 237.951,58.13 h1.52
  text "Top Layer - Bottom Layer" at 256.589,58.13 h1.52
  text "Via" at 294.678,58.13 h1.52
  text "Rounded" at 309.66,58.13 h1.52
  text "8" at 180.664,54.32 h1.52
  text "0.457mm (18.00mil)" at 195.9,54.32 h1.52
  text "PTH" at 225.101,54.32 h1.52
  text "Round" at 237.951,54.32 h1.52
  text "Top Layer - Bottom Layer" at 256.589,54.32 h1.52
  text "Via" at 294.678,54.32 h1.52
  text "Rounded" at 309.66,54.32 h1.52
  text "14" at 180.664,50.51 h1.52
  text "0.400mm (15.75mil)" at 195.9,50.51 h1.52
  text "PTH" at 225.101,50.51 h1.52
  text "Round" at 237.951,50.51 h1.52
  text "Top Layer - Bottom Layer" at 256.589,50.51 h1.52
  text "Pad" at 294.678,50.51 h1.52
  text "Rounded" at 309.66,50.51 h1.52
  text "21" at 180.664,46.7 h1.52
  text "0.900mm (35.43mil)" at 195.9,46.7 h1.52
  text "PTH" at 225.101,46.7 h1.52
  text "Round" at 237.951,46.7 h1.52
  text "Top Layer - Bottom Layer" at 256.589,46.7 h1.52
  text "Pad" at 294.678,46.7 h1.52
  text "(Mixed)" at 309.66,46.7 h1.52
  text "40" at 180.664,42.89 h1.52
  text "0.508mm (20.00mil)" at 195.9,42.89 h1.52
  text "PTH" at 225.101,42.89 h1.52
  text "Round" at 237.951,42.89 h1.52
  text "Top Layer - Bottom Layer" at 256.589,42.89 h1.52
  text "Via" at 294.678,42.89 h1.52
  text "Rounded" at 309.66,42.89 h1.52
  text "137" at 180.664,39.08 h1.52
  text "0.200mm (7.87mil)" at 195.9,39.08 h1.52
  text "PTH" at 225.101,39.08 h1.52
  text "Round" at 237.951,39.08 h1.52
  text "Top Layer - Bottom Layer" at 256.589,39.08 h1.52
  text "Via" at 294.678,39.08 h1.52
  text "Rounded" at 309.66,39.08 h1.52
  text "427" at 180.664,35.27 h1.52
  text "0.300mm (11.81mil)" at 195.9,35.27 h1.52
  text "PTH" at 225.101,35.27 h1.52
  text "Round" at 237.951,35.27 h1.52
  text "Top Layer - Bottom Layer" at 256.589,35.27 h1.52
  text "Via" at 294.678,35.27 h1.52
  text "Rounded" at 309.66,35.27 h1.52
  text "678 Total" at 180.664,31.46 h1.52
  text "Slot definitions :" at 167.815,27.778 h1.52
  text "Routed Path Length" at 194.045,27.778 h1.52
  text "= Calculated from tool start centre position to tool end centre position." at 222.053,27.778 h1.52
  text "Hole Length" at 194.045,25.238 h1.52
  text "= Routed Path Length + Tool Size = Slot length as defined in the PCB layout" at 211.642,25.238 h1.52

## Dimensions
0,0 to 0,75 on Mechanical 1
0,0 to 145,0 on Mechanical 1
